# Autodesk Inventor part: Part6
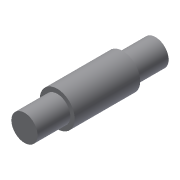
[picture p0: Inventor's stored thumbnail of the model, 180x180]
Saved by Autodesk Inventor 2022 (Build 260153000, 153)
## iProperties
Created: 2002-01
Part Number: Part6
Document SubType Name: Modeling
Designer: ***
Density: 1 g/cm^3
Material: Generic
Appearance: Default
Control State: 0
Master: False
Checked Out: False
Shininess: 77.0
Length Units: 11269
Angle Units: 11279
Time Units: 11290
Mass Units: 11283
Length Display Precision: 3
Angle Display Precision: 2
Density: 0.0
Volumn: 0.0
Area: 0.0
PropertySet Name: Model Information
Author: ***
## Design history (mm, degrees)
sketch "Sketch1"
  geometry: L1 (1.545, 32.521)-(-4.455, 32.521); L2 (-4.455, 32.521)-(-4.455, 17.521); L3 (-4.455, 17.521)-(-6.455, 17.521); L4 (-6.455, 17.521)-(-6.455, -12.479); L5 (-6.455, -12.479)-(-4.455, -12.479); L6 (-4.455, -12.479)-(-4.455, -27.479); L7 (-4.455, -27.479)-(1.545, -27.479); L8 (1.545, -27.479)-(1.545, 32.521)
  constraints: 16 end point, 5 parallel, 2 equal length, 1 collinear, 1 horizontal, 1 perpendicular
  dimensions: "d0" = 16 diameter of L4 L8; "d1" = 12 diameter of L2 L8; "d2" = 60 distance of L7.end L1.start; "d3" = 30 distance of L3.end L4.end
revolve "Revolution1" sketch "Sketch1" stored, may be unused: angle "d4" = 90 deg
body "Solid1"
